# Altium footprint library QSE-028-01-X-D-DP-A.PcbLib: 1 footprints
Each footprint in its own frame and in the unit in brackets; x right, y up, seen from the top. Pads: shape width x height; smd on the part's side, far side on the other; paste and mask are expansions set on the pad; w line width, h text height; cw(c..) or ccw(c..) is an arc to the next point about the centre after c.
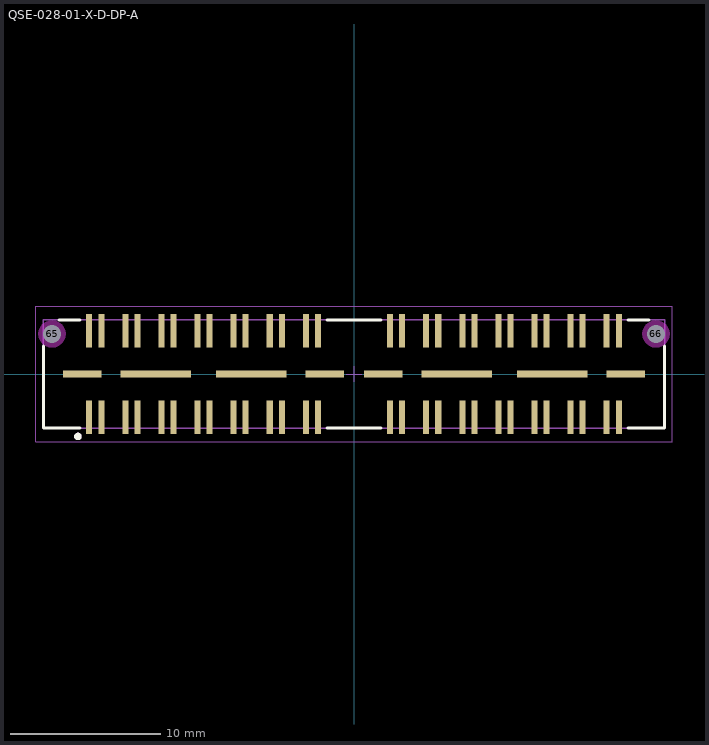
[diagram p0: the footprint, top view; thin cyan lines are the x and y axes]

## QSE-028-01-X-D-DP-A [mm] "0.80mm pitch, 56 pin, high speed socket strip; differential"
height 3.25
pads (66):
  rect 0.4x2.25 smd mask+0: 1(-17.6,-2.87) 2(-17.6,2.87) 3(-16.8,-2.87) 4(-16.8,2.87) 5(-15.2,-2.87) 6(-15.2,2.87) 7(-14.4,-2.87) 8(-14.4,2.87) 9(-12.8,-2.87) 10(-12.8,2.87) 11(-12,-2.87) 12(-12,2.87) 13(-10.4,-2.87) 14(-10.4,2.87) 15(-9.6,-2.87) 16(-9.6,2.87) 17(-8,-2.87) 18(-8,2.87) 19(-7.2,-2.87) 20(-7.2,2.87) 21(-5.6,-2.87) 22(-5.6,2.87) 23(-4.8,-2.87) 24(-4.8,2.87) 25(-3.2,-2.87) 26(-3.2,2.87) 27(-2.4,-2.87) 28(-2.4,2.87) 29(2.4,-2.87) 30(2.4,2.87) 31(3.2,-2.87) 32(3.2,2.87) 33(4.8,-2.87) 34(4.8,2.87) 35(5.6,-2.87) 36(5.6,2.87) 37(7.2,-2.87) 38(7.2,2.87) 39(8,-2.87) 40(8,2.87) 41(9.6,-2.87) 42(9.6,2.87) 43(10.4,-2.87) 44(10.4,2.87) 45(12,-2.87) 46(12,2.87) 47(12.8,-2.87) 48(12.8,2.87) 49(14.4,-2.87) 50(14.4,2.87) 51(15.2,-2.87) 52(15.2,2.87) 53(16.8,-2.87) 54(16.8,2.87) 55(17.6,-2.87) 56(17.6,2.87)
  rect 2.55x0.45 smd mask+0: 57(-18.065,0) 60(-1.935,0) 61(1.935,0) 64(18.065,0)
  rect 4.7x0.45 smd mask+0: 58(-13.175,0) 59(-6.825,0) 62(6.825,0) 63(13.175,0)
  round 1 hole 1.2 unplated mask+0: 65(-20.065,2.67) 66(20.065,2.67)
Top Overlay:
  circle w0.25: c-18.35,-4.15 r0.125
  lines w0.2: -20.65,1.85 -20.65,-3.6 -18.2,-3.6 ; -19.6,3.6 -18.2,3.6 ; -1.8,-3.6 1.8,-3.6 ; -1.8,3.6 1.8,3.6 ; 18.2,-3.6 20.65,-3.6 20.65,1.85 ; 18.2,3.6 19.6,3.6
Keep-Out Layer:
  pour cut-out: 20.973,2.67 20.942,2.905 20.851,3.124 20.707,3.312 20.519,3.456 20.3,3.547 20.065,3.578 19.83,3.547 19.611,3.456 19.423,3.312 19.279,3.124 19.188,2.905 19.157,2.67 19.188,2.435 19.279,2.216 19.423,2.028 19.611,1.884 19.83,1.793 20.065,1.762 20.3,1.793 20.519,1.884 20.707,2.028 20.851,2.216 20.942,2.435
  pour cut-out: -19.157,2.67 -19.188,2.905 -19.279,3.124 -19.423,3.312 -19.611,3.456 -19.83,3.547 -20.065,3.578 -20.3,3.547 -20.519,3.456 -20.707,3.312 -20.851,3.124 -20.942,2.905 -20.973,2.67 -20.942,2.435 -20.851,2.216 -20.707,2.028 -20.519,1.884 -20.3,1.793 -20.065,1.762 -19.83,1.793 -19.611,1.884 -19.423,2.028 -19.279,2.216 -19.188,2.435
Mechanical 12:
  lines w0.001: -20.65,-3.6 -20.65,3.6 20.65,3.6 20.65,-3.6 -20.65,-3.6
Mechanical 13:
  circle w0.25: c-18.35,-4.15 r0.125
  lines w0.1: -20.65,-3.6 -20.65,3.6 20.65,3.6 20.65,-3.6 -20.65,-3.6
  text ".Designator" at 0,0 h1.52
Mechanical 15:
  lines w0.05: -0.5,0 0.5,0 ; 0,-0.5 0,0.5 ; -21.15,-4.5 -21.15,4.5 21.15,4.5 21.15,-4.5 -21.15,-4.5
